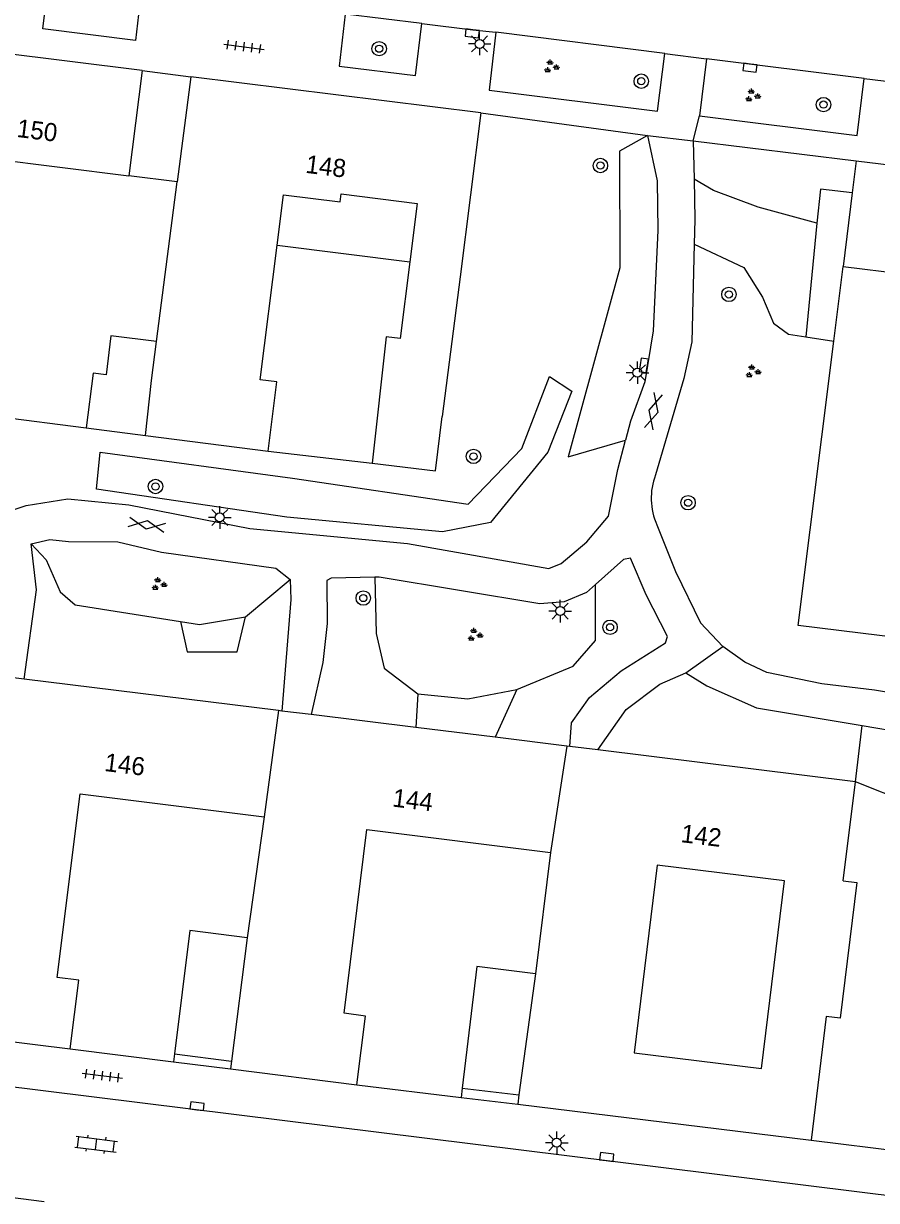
# Model space of a CAD drawing. Extents: x 131000 to 133014, y 396499 to 399001.
# Drawn here: x 131421.7 to 131469, y 396747.9 to 396813.1 of the extents above; entities that cross this region are included whole.
import ezdxf

# ---------------------------------------------------------------- set-up
doc = ezdxf.new("R2010")
doc.units = 0
for name, color, linetype in [('gg-afsc-erfafscheiding', 7, 'Continuous'), ('gg-afsc-hekwerk', 7, 'Continuous'), ('gg-afsc-muur', 7, 'Continuous'), ('gg-anno-huisnummerreeks BGT', 7, 'Continuous'), ('gg-bbg-bijgebouw', 7, 'Continuous'), ('gg-bbg-gedigitaliseerde bebouwing', 7, 'Continuous'), ('gg-bbg-gedigitaliseerde bijgebouw', 7, 'Continuous'), ('gg-bbg-hoofdgebouw', 7, 'Continuous'), ('gg-bbg-luifel en loopbrug', 7, 'Continuous'), ('gg-bbg-tussenscheiding', 7, 'Continuous'), ('gg-knt-verharding', 7, 'Continuous'), ('gt-grn-groengrens', 7, 'Continuous'), ('gt-grn-weggrens', 7, 'Continuous'), ('gt-symb-boom', 7, 'Continuous'), ('gt-symb-gesloten verharding', 7, 'Continuous'), ('gt-symb-groenvak', 7, 'Continuous'), ('gt-symb-klinker verharding', 7, 'Continuous'), ('gt-symb-kolk', 7, 'Continuous'), ('gt-symb-lichtmast', 7, 'Continuous'), ('gt-symb-tegel verharding', 7, 'Continuous')]:
    doc.layers.add(name, color=color, linetype=linetype)

# ---------------------------------------------------------------- blocks, each defined once
blk = doc.blocks.new('gt0-BOOM')
at = {"layer": 'gt-symb-boom'}
for radius in [0.4, 0.2]:
    blk.add_circle((0, 0), radius, dxfattribs=at)
blk = doc.blocks.new('gt0-GRVAK')
at = {"layer": 'gt-symb-groenvak'}
for p, q in [((-0.11, 0.189), (-0.228, 0.24)), ((-0.182, 0.153), (0.088, 0.153)), ((-0.091, 0.211), (-0.156, 0.322)), ((-0.047, 0.214), (-0.047, 0.393)), ((-0.004, 0.211), (0.061, 0.322)), ((0.015, 0.189), (0.133, 0.24)), ((0.262, -0.052), (0.197, 0.059)), ((0.305, -0.049), (0.305, 0.13)), ((0.349, -0.052), (0.414, 0.059)), ((-0.245, -0.228), (-0.363, -0.177)), ((-0.318, -0.264), (-0.047, -0.264)), ((-0.226, -0.206), (-0.291, -0.095)), ((-0.183, -0.203), (-0.183, -0.024)), ((-0.139, -0.206), (-0.074, -0.095)), ((-0.12, -0.228), (-0.002, -0.177)), ((0.243, -0.074), (0.125, -0.023)), ((0.17, -0.11), (0.441, -0.11)), ((0.368, -0.074), (0.486, -0.023))]:
    blk.add_line(p, q, dxfattribs=at)
blk = doc.blocks.new('gt0-KOLK')
at = {"layer": 'gt-symb-kolk'}
blk.add_lwpolyline([(0, 0), (0.375, 0), (0.375, 0.4), (-0.375, 0.4), (-0.375, 0), (0, 0)], dxfattribs=at)
blk = doc.blocks.new('gt0-TEG1')
at = {"layer": 'gt-symb-tegel verharding'}
for p, q in [((-1.125, 0), (1.125, 0)), ((-0.9, -0.25), (-0.9, 0.25)), ((-0.45, -0.25), (-0.45, 0.25)), ((0, -0.25), (0, 0.25)), ((0.45, -0.25), (0.45, 0.25)), ((0.9, -0.25), (0.9, 0.25))]:
    blk.add_line(p, q, dxfattribs=at)
blk = doc.blocks.new('gt0-LMAST')
at = {"layer": 'gt-symb-lichtmast'}
for p, q in [((-0.182, 0.173), (-0.447, 0.438)), ((-0.005, 0.246), (-0.005, 0.621)), ((0.172, 0.173), (0.437, 0.438)), ((-0.255, -0.004), (-0.63, -0.004)), ((-0.182, -0.181), (-0.447, -0.446)), ((-0.005, -0.254), (-0.005, -0.629)), ((0.437, -0.446), (0.172, -0.181)), ((0.245, -0.004), (0.62, -0.004))]:
    blk.add_line(p, q, dxfattribs=at)
blk.add_circle((-0.005, -0.004), 0.25, dxfattribs=at)
blk = doc.blocks.new('gt0-GESVH1')
at = {"layer": 'gt-symb-gesloten verharding'}
for p, q in [((-0.992, -0.261), (0.008, 0.239)), ((0.008, -0.261), (-0.992, 0.239)), ((0.008, 0.239), (1.008, -0.261)), ((1.008, 0.239), (0.008, -0.261))]:
    blk.add_line(p, q, dxfattribs=at)
blk = doc.blocks.new('gt0-KL1')
at = {"layer": 'gt-symb-klinker verharding'}
for p, q in [((-1.15, 0.3), (1.15, 0.3)), ((-1, -0.3), (-1, 0.3)), ((-0.5, 0.3), (-0.5, 0.45)), ((0, -0.3), (0, 0.3)), ((0.5, 0.3), (0.5, 0.45)), ((1, -0.3), (1, 0.3)), ((-1.15, -0.3), (1.15, -0.3)), ((-0.5, -0.45), (-0.5, -0.3)), ((0.5, -0.45), (0.5, -0.3))]:
    blk.add_line(p, q, dxfattribs=at)

msp = doc.modelspace()

# ---------------------------------------------------------------- linework, layer by layer
at = {"layer": 'gg-afsc-erfafscheiding'}
for p in [(131440.18, 396754.31), (131446.02, 396754.13)]:
    msp.add_line(p, (131445.959, 396753.616), dxfattribs=at)
at = {"layer": 'gg-afsc-hekwerk'}
for p in [(131424.31, 396756.3), (131430.09, 396756.02)]:
    msp.add_line(p, (131430.036, 396755.584), dxfattribs=at)
at = {"layer": 'gg-afsc-muur'}
for p, q in [((131419.34, 396791.44), (131425.2, 396790.69)), ((131435.27, 396789.39), (131441.03, 396788.73))]:
    msp.add_line(p, q, dxfattribs=at)
at = {"layer": 'gg-bbg-bijgebouw'}
for p, q in [((131425.59, 396793.71), (131425.2, 396790.69)), ((131425.2, 396790.69), (131428.478, 396790.267)), ((131430.09, 396756.02), (131433.24, 396755.62)), ((131446.02, 396754.13), (131449.15, 396753.75))]:
    msp.add_line(p, q, dxfattribs=at)
for points in [[(131434.11, 396762.45), (131430.94, 396762.85), (131430.09, 396756.02)], [(131450.07, 396760.45), (131446.82, 396760.86), (131446.02, 396754.13)]]:
    msp.add_lwpolyline(points, dxfattribs=at)
at = {"layer": 'gg-bbg-gedigitaliseerde bebouwing'}
for p, q in [((131429.081, 396795.479), (131430.24, 396804.31)), ((131443.514, 396803.111), (131443.107, 396799.887))]:
    msp.add_line(p, q, dxfattribs=at)
for points in [[(131443.107, 396799.887), (131442.571, 396795.637), (131441.807, 396795.732), (131441.03, 396788.73)], [(131456.814, 396766.467), (131455.544, 396756.082), (131462.586, 396755.221), (131463.856, 396765.606), (131456.814, 396766.467)]]:
    msp.add_lwpolyline(points, dxfattribs=at)
at = {"layer": 'gg-bbg-gedigitaliseerde bijgebouw'}
msp.add_lwpolyline([(131429.081, 396795.479), (131426.566, 396795.793), (131426.295, 396793.622), (131425.59, 396793.71)], dxfattribs=at)
at = {"layer": 'gg-bbg-hoofdgebouw'}
for p, q in [((131428.287, 396810.47), (131415.066, 396812.112)), ((131428.287, 396810.47), (131427.556, 396804.645)), ((131430.991, 396810.134), (131430.24, 396804.31)), ((131447.04, 396808.14), (131430.991, 396810.134)), ((131434.826, 396793.356), (131435.766, 396800.812)), ((131466.593, 396795.495), (131467.11, 396799.62)), ((131467.11, 396799.62), (131480.41, 396797.98)), ((131428.478, 396790.267), (131435.27, 396789.39)), ((131421.752, 396776.773), (131420.199, 396776.964)), ((131435.843, 396775.034), (131421.752, 396776.773)), ((131436.035, 396775.01), (131435.843, 396775.034)), ((131437.653, 396774.81), (131436.035, 396775.01)), ((131443.444, 396774.096), (131437.653, 396774.81)), ((131447.842, 396773.553), (131443.444, 396774.096)), ((131451.801, 396773.064), (131447.842, 396773.553)), ((131451.968, 396773.043), (131451.801, 396773.064)), ((131453.518, 396772.852), (131451.968, 396773.043)), ((131467.79, 396771.09), (131453.518, 396772.852)), ((131467.115, 396765.611), (131467.79, 396771.09)), ((131435.04, 396769.15), (131434.11, 396762.45)), ((131450.91, 396767.17), (131450.07, 396760.45)), ((131417.45, 396757.16), (131424.31, 396756.3)), ((131433.24, 396755.62), (131433.19, 396755.19)), ((131433.19, 396755.19), (131440.18, 396754.31)), ((131449.15, 396753.75), (131449.09, 396753.24)), ((131449.09, 396753.24), (131465.34, 396751.243))]:
    msp.add_line(p, q, dxfattribs=at)
for points in [[(131447.04, 396808.14), (131445.895, 396799.052), (131444.91, 396791.32)], [(131419.34, 396791.44), (131419.82, 396795.28), (131418.63, 396795.43), (131419.9, 396805.6), (131427.556, 396804.645)], [(131435.766, 396800.812), (131436.117, 396803.6), (131439.252, 396803.205), (131439.307, 396803.641), (131443.514, 396803.111)], [(131471.51, 396778.89), (131464.62, 396779.75), (131466.593, 396795.495)], [(131435.27, 396789.39), (131435.75, 396793.24), (131434.826, 396793.356)], [(131441.03, 396788.73), (131444.54, 396788.3), (131444.91, 396791.32)], [(131424.31, 396756.3), (131424.78, 396760.11), (131423.59, 396760.26), (131424.86, 396770.43), (131435.04, 396769.15)], [(131440.18, 396754.31), (131440.66, 396758.12), (131439.47, 396758.27), (131440.74, 396768.44), (131450.91, 396767.17)], [(131467.115, 396765.611), (131467.859, 396765.52), (131466.94, 396758.006), (131466.164, 396758.101), (131465.34, 396751.243)]]:
    msp.add_lwpolyline(points, dxfattribs=at)
at = {"layer": 'gg-bbg-luifel en loopbrug'}
for p, q in [((131428.287, 396810.47), (131430.991, 396810.134)), ((131430.24, 396804.31), (131427.556, 396804.645)), ((131435.766, 396800.812), (131443.107, 396799.887))]:
    msp.add_line(p, q, dxfattribs=at)
at = {"layer": 'gg-bbg-tussenscheiding'}
for p, q in [((131428.81, 396793.31), (131429.081, 396795.479)), ((131428.478, 396790.267), (131428.81, 396793.31)), ((131435.843, 396775.034), (131435.04, 396769.15)), ((131451.801, 396773.064), (131450.91, 396767.17)), ((131434.11, 396762.45), (131433.24, 396755.62)), ((131450.07, 396760.45), (131449.15, 396753.75))]:
    msp.add_line(p, q, dxfattribs=at)
at = {"layer": 'gg-knt-verharding'}
for p, q in [((131443.783, 396813.074), (131439.526, 396813.605)), ((131457.225, 396811.413), (131447.877, 396812.598)), ((131457.225, 396811.413), (131459.539, 396811.127)), ((131459.539, 396811.127), (131459.161, 396807.958)), ((131468.275, 396810.042), (131459.539, 396811.127)), ((131468.275, 396810.042), (131471.636, 396809.619)), ((131447.04, 396808.14), (131456.278, 396806.872)), ((131456.278, 396806.872), (131458.81, 396806.59)), ((131458.81, 396806.59), (131458.849, 396804.458)), ((131458.81, 396806.59), (131467.833, 396805.477)), ((131467.833, 396805.477), (131524.324, 396798.546)), ((131361.43, 396761.6), (131524.516, 396741.383)), ((131430.036, 396755.584), (131433.19, 396755.19)), ((131445.959, 396753.616), (131449.09, 396753.24)), ((131465.34, 396751.243), (131476.84, 396749.82)), ((131418.335, 396748.418), (131422.876, 396747.855))]:
    msp.add_line(p, q, dxfattribs=at)
for points in [[(131428.255, 396815.027), (131427.934, 396812.146), (131422.798, 396812.784), (131423.151, 396815.659)], [(131439.526, 396813.605), (131439.195, 396810.72), (131443.437, 396810.196), (131443.783, 396813.074)], [(131443.783, 396813.074), (131446.595, 396812.735), (131447.877, 396812.598)], [(131447.877, 396812.598), (131447.507, 396809.389), (131456.821, 396808.224), (131457.225, 396811.413)], [(131459.161, 396807.958), (131467.875, 396806.877), (131468.275, 396810.042)], [(131456.278, 396806.872), (131456.81, 396804.36), (131456.85, 396801.61), (131456.59, 396796.07), (131456.12, 396793.23), (131455.34, 396791.06), (131455.062, 396790.009)], [(131458.849, 396804.458), (131458.89, 396802.22), (131458.858, 396800.856)], [(131458.858, 396800.856), (131458.73, 396795.45), (131458.28, 396793.42), (131456.72, 396788.08)], [(131406.96, 396776.78), (131409.25, 396778.11), (131411.83, 396780.37), (131414.93, 396783.67), (131416.66, 396785), (131419.36, 396785.56), (131421.88, 396786.39), (131424.17, 396786.75), (131427.56, 396786.42), (131434.25, 396785.12), (131442.99, 396784.28), (131450.82, 396782.9), (131451.5, 396783.18), (131452.91, 396784.38), (131454.11, 396785.79), (131454.63, 396788.38), (131455.062, 396790.009)], [(131456.8, 396785.31), (131457.83, 396782.73), (131459.21, 396779.89), (131460.44, 396778.58)], [(131421.752, 396776.773), (131422.446, 396781.719), (131422.141, 396784.264)], [(131422.141, 396784.264), (131423.18, 396784.5), (131424.21, 396784.39), (131426.94, 396784.38), (131429.36, 396783.81), (131435.698, 396782.92), (131436.487, 396782.285)], [(131451.968, 396773.043), (131452.072, 396774.355), (131453.066, 396775.754), (131454.812, 396777.239), (131457.277, 396778.781), (131457.389, 396779.13), (131456.2, 396781.45), (131455.34, 396783.47), (131454.94, 396783.4), (131453.402, 396782.021)], [(131436.487, 396782.285), (131436.533, 396781.186), (131436.035, 396775.01)], [(131441.18, 396782.415), (131438.75, 396782.362), (131438.512, 396782.238), (131438.541, 396779.85), (131438.305, 396777.695), (131437.653, 396774.81)], [(131453.402, 396782.021), (131452.9, 396781.57), (131451.66, 396781.06), (131450.32, 396780.95), (131441.41, 396782.42), (131441.18, 396782.415)], [(131527.48, 396765.21), (131522.04, 396765.8), (131515.5, 396765.7), (131503.45, 396764.11), (131499.45, 396764.1), (131495.47, 396764.94), (131490.65, 396766.99), (131485.72, 396769.6), (131480.69, 396771.94), (131476.7, 396774.27), (131472.91, 396775.48), (131468.85, 396776.17), (131465.92, 396776.52), (131462.89, 396777.14), (131461.67, 396777.72), (131460.44, 396778.58)], [(131453.518, 396772.852), (131455.088, 396775.09), (131456.95, 396776.496), (131458.4, 396777.12)], [(131458.4, 396777.12), (131459.56, 396776.4), (131462.31, 396775.18), (131468.169, 396774.199)], [(131468.169, 396774.199), (131470.55, 396773.8), (131473.95, 396773.14), (131475.83, 396772.5), (131477.36, 396771.5), (131478.1, 396770.32), (131478.62, 396769.16), (131479.939, 396765.579)]]:
    msp.add_lwpolyline(points, dxfattribs=at)
msp.add_arc((131460.045, 396786.79), 3.567, 158.79606, 204.51252, dxfattribs=at)
at = {"layer": 'gt-grn-groengrens'}
for p, q in [((131467.833, 396805.477), (131467.613, 396803.696)), ((131467.613, 396803.696), (131467.11, 396799.62)), ((131465.658, 396802.025), (131465.033, 396795.729)), ((131465.033, 396795.729), (131466.593, 396795.495)), ((131434.013, 396780.218), (131436.487, 396782.285)), ((131449.047, 396776.192), (131447.842, 396773.553)), ((131443.561, 396775.966), (131443.444, 396774.096)), ((131467.79, 396771.09), (131468.169, 396774.199))]:
    msp.add_line(p, q, dxfattribs=at)
for points in [[(131456.278, 396806.872), (131454.731, 396806.012), (131454.733, 396799.555), (131451.878, 396789.091), (131455.062, 396790.009)], [(131465.658, 396802.025), (131462.405, 396802.912), (131459.931, 396803.84), (131458.849, 396804.458)], [(131467.613, 396803.696), (131465.845, 396803.906), (131465.658, 396802.025)], [(131458.858, 396800.856), (131461.613, 396799.57), (131462.64, 396797.927), (131463.256, 396796.489), (131464.077, 396795.873), (131465.033, 396795.729)], [(131425.762, 396787.285), (131425.967, 396789.335), (131436.619, 396787.9), (131446.349, 396786.466), (131449.32, 396789.54), (131450.856, 396793.535), (131452.085, 396792.716), (131450.754, 396789.335), (131447.578, 396785.441), (131444.915, 396784.929), (131436.312, 396785.749), (131425.762, 396787.285)], [(131422.141, 396784.264), (131422.973, 396783.38), (131423.75, 396781.617), (131424.58, 396780.891), (131430.417, 396779.97)], [(131441.18, 396782.415), (131441.242, 396779.303), (131441.694, 396777.38), (131443.561, 396775.966)], [(131449.047, 396776.192), (131452.158, 396777.493), (131453.402, 396778.907), (131453.402, 396782.021)], [(131430.417, 396779.97), (131430.778, 396778.285), (131433.55, 396778.285), (131434.013, 396780.218)], [(131430.417, 396779.97), (131431.473, 396779.803), (131434.013, 396780.218)], [(131443.561, 396775.966), (131446.332, 396775.683), (131449.047, 396776.192)], [(131479.939, 396765.579), (131476.158, 396764.491), (131474.782, 396767.878), (131472.915, 396768.953), (131470.766, 396769.914), (131467.79, 396771.09)]]:
    msp.add_lwpolyline(points, dxfattribs=at)
at = {"layer": 'gt-grn-weggrens'}
for p, q in [((131458.81, 396806.59), (131459.161, 396807.958)), ((131458.4, 396777.12), (131460.44, 396778.58))]:
    msp.add_line(p, q, dxfattribs=at)

# ---------------------------------------------------------------- block references
at = {"layer": 'gt-symb-boom'}
for p in [(131441.417, 396811.685), (131455.932, 396809.883), (131466.018, 396808.589), (131453.668, 396805.215), (131460.782, 396798.077), (131446.64, 396789.106), (131458.522, 396786.544), (131440.538, 396781.266), (131454.199, 396779.645)]:
    msp.add_blockref('gt0-BOOM', p, dxfattribs=at)
at = {"layer": 'gt-symb-boom', "rotation": -107.87342106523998}
msp.add_blockref('gt0-BOOM', (131429.033, 396787.443), dxfattribs=at)
at = {"layer": 'gt-symb-gesloten verharding'}
for p, rotation in [((131456.597, 396791.606), 74.86552497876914), ((131428.545, 396785.329), -9.44347490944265)]:
    msp.add_blockref('gt0-GESVH1', p, dxfattribs=dict(at, rotation=rotation))
at = {"layer": 'gt-symb-groenvak'}
for p in [(131450.931, 396810.687), (131462.074, 396809.08), (131462.097, 396793.805), (131429.208, 396782.028), (131446.702, 396779.218)]:
    msp.add_blockref('gt0-GRVAK', p, dxfattribs=at)
at = {"layer": 'gt-symb-klinker verharding', "rotation": -7.068140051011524}
msp.add_blockref('gt0-KL1', (131425.741, 396751.021), dxfattribs=at)
at = {"layer": 'gt-symb-kolk'}
for p, rotation in [((131446.595, 396812.735), 173.10945167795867), ((131461.976, 396810.83), 172.8749836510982), ((131455.87, 396794.187), -99.55652761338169), ((131431.313, 396752.927), -7.068140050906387), ((131453.992, 396750.115), -7.238726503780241)]:
    msp.add_blockref('gt0-KOLK', p, dxfattribs=dict(at, rotation=rotation))
at = {"layer": 'gt-symb-lichtmast'}
for p in [(131446.984, 396811.952), (131455.72, 396793.747), (131432.593, 396785.731), (131451.444, 396780.549), (131451.253, 396751.109)]:
    msp.add_blockref('gt0-LMAST', p, dxfattribs=at)
at = {"layer": 'gt-symb-tegel verharding'}
for p, rotation in [((131433.931, 396811.793), -7.530253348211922), ((131426.084, 396754.822), -7.295560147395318)]:
    msp.add_blockref('gt0-TEG1', p, dxfattribs=dict(at, rotation=rotation))

# ---------------------------------------------------------------- texts
at = {"layer": 'gg-anno-huisnummerreeks BGT'}
for s, rotation, p in [('150', 352.9, (131421.317, 396806.802)), ('148', 352.9, (131437.304, 396804.816)), ('146', 353, (131426.169, 396771.693)), ('144', 353, (131442.114, 396769.725)), ('142', 353, (131458.087, 396767.753))]:
    msp.add_text(s, height=1, rotation=rotation, dxfattribs=at).set_placement(p)

doc.saveas('drawing.dxf')
